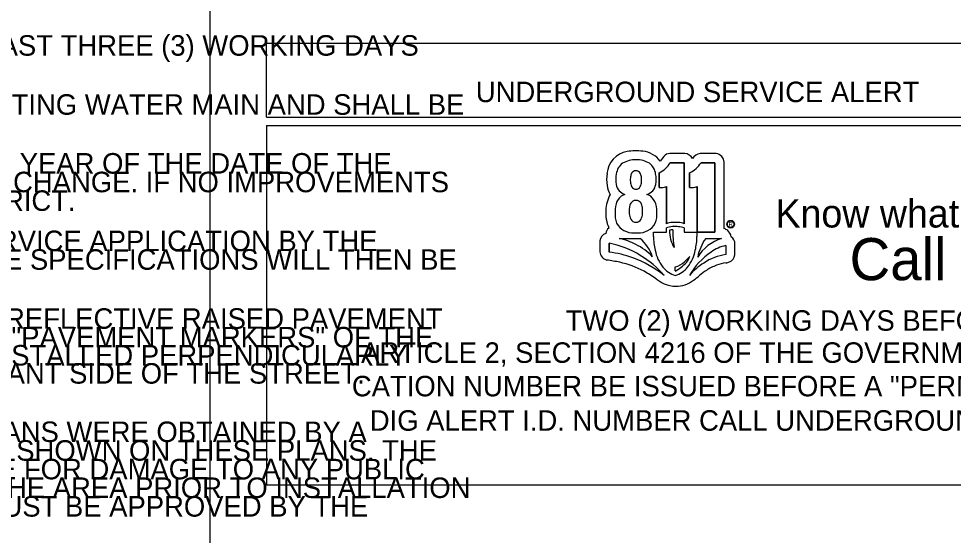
# Model space of a CAD drawing. Extents: x 837 to 1117, y 1316 to 1424.
# Drawn here: x 853.74 to 859.2, y 1404.15 to 1407.17 of the extents above; entities that cross this region are included whole.
import ezdxf

# ---------------------------------------------------------------- set-up
doc = ezdxf.new("R2010")
doc.units = 0
for name, color, linetype in [('BASEMAP', 7, 'Continuous'), ('Border', 7, 'Continuous'), ('Call811-black', 7, 'Continuous'), ('LLINES', 7, 'Continuous'), ('TEXT', 7, 'Continuous')]:
    doc.layers.add(name, color=color, linetype=linetype)

msp = doc.modelspace()

# ---------------------------------------------------------------- linework, layer by layer
msp.add_line((855.1874, 1406.5437), (855.1874, 1404.4416))
at = {"layer": 'BASEMAP'}
for p, q in [((854.8567, 1399.867), (854.8567, 1420.0652)), ((855.1874, 1406.5937), (855.1874, 1407.0257)), ((855.1874, 1407.0257), (862.4354, 1407.0257)), ((855.1874, 1406.5937), (862.4354, 1406.5937)), ((855.1874, 1406.5437), (862.4354, 1406.5437)), ((855.1855, 1404.4416), (862.4345, 1404.4416))]:
    msp.add_line(p, q, dxfattribs=at)
at = {"layer": 'Call811-black'}
for p, q in [((857.5107, 1406.3636), (857.49, 1406.3364)), ((857.6341, 1406.3807), (857.5472, 1406.3807)), ((857.6797, 1406.3505), (857.6781, 1406.3505)), ((857.8174, 1406.3802), (857.7235, 1406.3802)), ((857.549, 1406.3269), (857.6297, 1406.3269)), ((857.6297, 1406.3269), (857.6297, 1405.9699)), ((857.7289, 1406.3269), (857.8097, 1406.3269)), ((857.8097, 1406.3269), (857.8097, 1405.9204)), ((857.8636, 1405.9408), (857.8636, 1406.33)), ((857.4844, 1406.1821), (857.4844, 1406.2682)), ((857.6619, 1406.1821), (857.6619, 1406.2682)), ((857.5261, 1405.9699), (857.5261, 1406.1875)), ((857.706, 1405.9204), (857.706, 1406.1875)), ((857.451, 1405.8952), (857.451, 1405.9193)), ((857.451, 1405.9193), (857.5261, 1405.9193)), ((857.5261, 1405.9193), (857.5261, 1405.9453)), ((857.6297, 1405.9453), (857.6297, 1405.9193)), ((857.6297, 1405.9193), (857.7048, 1405.9193)), ((857.7048, 1405.9193), (857.7048, 1405.8952)), ((857.8097, 1405.9204), (857.706, 1405.9204)), ((857.1375, 1405.8693), (857.1375, 1405.8054)), ((857.1905, 1405.8025), (857.1905, 1405.8558)), ((857.2508, 1405.884), (857.3735, 1405.884)), ((857.7561, 1405.8831), (857.8492, 1405.8831)), ((857.9273, 1405.7867), (857.9273, 1405.8519)), ((857.8738, 1405.8415), (857.8738, 1405.7886))]:
    msp.add_line(p, q, dxfattribs=at)
for points in [[(857.5107, 1406.3636), (857.49, 1406.3364)], [(857.6341, 1406.3807), (857.5472, 1406.3807)], [(857.6797, 1406.3505), (857.6781, 1406.3505)], [(857.8174, 1406.3802), (857.7235, 1406.3802)], [(857.6297, 1405.9699), (857.6297, 1406.3269), (857.549, 1406.3269)], [(857.706, 1405.9204), (857.8097, 1405.9204), (857.8097, 1406.3269), (857.7289, 1406.3269)], [(857.8636, 1405.9408), (857.8636, 1406.33)], [(857.4844, 1406.2682), (857.4844, 1406.1821)], [(857.6619, 1406.2682), (857.6619, 1406.1821)], [(857.5261, 1406.1875), (857.5261, 1405.9699)], [(857.706, 1406.1875), (857.706, 1405.9204)], [(857.451, 1405.8952), (857.451, 1405.9193), (857.5261, 1405.9193), (857.5261, 1405.9453)], [(857.6297, 1405.9453), (857.6297, 1405.9193), (857.7048, 1405.9193), (857.7048, 1405.8952)], [(857.1375, 1405.8693), (857.1375, 1405.8054)], [(857.1905, 1405.8558), (857.1905, 1405.8025)], [(857.2508, 1405.884), (857.3735, 1405.884)], [(857.7561, 1405.8831), (857.8492, 1405.8831)], [(857.9273, 1405.7867), (857.9273, 1405.8519)], [(857.8738, 1405.8415), (857.8738, 1405.7886)], [(857.578, 1405.693), (857.5783, 1405.7168)]]:
    msp.add_lwpolyline(points, dxfattribs=at)
for radius in [0.0224, 0.0224, 0.0191, 0.0191]:
    msp.add_circle((857.9019, 1405.967), radius, dxfattribs=at)
for centre, radius, start, end in [((857.3207, 1406.2516), 0.1425, 99.999, 175.1926), ((857.3207, 1406.2516), 0.1425, 99.999, 175.1926), ((857.349, 1406.0779), 0.3185, 82.8327, 99.5813), ((857.349, 1406.0779), 0.3185, 82.8327, 99.5813), ((857.3717, 1406.246), 0.1489, 37.4108, 83.4439), ((857.3717, 1406.246), 0.1489, 37.4108, 83.4439), ((857.3437, 1406.2018), 0.1422, 87.8118, 121.4594), ((857.3437, 1406.2018), 0.1422, 87.8118, 121.4594), ((857.353, 1406.2026), 0.1414, 58.4897, 91.5654), ((857.353, 1406.2026), 0.1414, 58.4897, 91.5654), ((857.5475, 1406.3322), 0.0484, 90.4592, 139.5917), ((857.5475, 1406.3322), 0.0484, 90.4592, 139.5917), ((857.6301, 1406.3276), 0.0532, 25.4835, 85.607), ((857.6301, 1406.3276), 0.0532, 25.4835, 85.607), ((857.7279, 1406.3266), 0.0538, 94.7078, 153.6211), ((857.7279, 1406.3266), 0.0538, 94.7078, 153.6211), ((857.8103, 1406.3273), 0.0534, 2.8738, 82.3381), ((857.8103, 1406.3273), 0.0534, 2.8738, 82.3381), ((857.3231, 1406.2502), 0.0905, 126.3161, 173.2477), ((857.3231, 1406.2502), 0.0905, 126.3161, 173.2477), ((857.3733, 1406.2502), 0.0905, 6.7523, 53.6839), ((857.3733, 1406.2502), 0.0905, 6.7523, 53.6839), ((857.4264, 1406.3969), 0.1412, 294.2543, 330.2691), ((857.4264, 1406.3969), 0.1412, 294.2543, 330.2691), ((857.6032, 1406.4028), 0.1469, 293.5734, 328.8767), ((857.6032, 1406.4028), 0.1469, 293.5734, 328.8767), ((857.4313, 1406.229), 0.2549, 172.2103, 188.1816), ((857.4313, 1406.229), 0.2549, 172.2103, 188.1816), ((857.3928, 1406.229), 0.1627, 168.7247, 190.4792), ((857.3928, 1406.229), 0.1627, 168.7247, 190.4792), ((857.4461, 1406.2268), 0.131, 172.09, 185.2177), ((857.4461, 1406.2268), 0.131, 172.09, 185.2177), ((857.3776, 1406.2363), 0.0618, 152.1584, 172.0655), ((857.3776, 1406.2363), 0.0618, 152.1584, 172.0655), ((857.3468, 1406.2523), 0.0271, 87.8996, 151.6932), ((857.3468, 1406.2523), 0.0271, 87.8996, 151.6932), ((857.3494, 1406.2522), 0.0272, 28.3588, 93.3211), ((857.3494, 1406.2522), 0.0272, 28.3588, 93.3211), ((857.3187, 1406.2363), 0.0618, 7.9345, 27.8416), ((857.3187, 1406.2363), 0.0618, 7.9345, 27.8416), ((857.2502, 1406.2268), 0.131, 354.7823, 7.91), ((857.2502, 1406.2268), 0.131, 354.7823, 7.91), ((857.3035, 1406.229), 0.1627, 349.5208, 11.2753), ((857.3035, 1406.229), 0.1627, 349.5208, 11.2753), ((857.311, 1406.2117), 0.1334, 188.1816, 212.2335), ((857.311, 1406.2117), 0.1334, 188.1816, 212.2335), ((857.3021, 1406.2091), 0.07, 187.8977, 254.9735), ((857.3021, 1406.2091), 0.07, 187.8977, 254.9735), ((857.3835, 1406.2172), 0.0679, 181.9453, 206.7716), ((857.3835, 1406.2172), 0.0679, 181.9453, 206.7716), ((857.3484, 1406.2009), 0.0292, 209.2686, 270.3024), ((857.3484, 1406.2009), 0.0292, 209.2686, 270.3024), ((857.3478, 1406.2009), 0.0293, 271.4639, 330.7182), ((857.3478, 1406.2009), 0.0293, 271.4639, 330.7182), ((857.3128, 1406.2172), 0.0679, 333.2284, 358.0547), ((857.3128, 1406.2172), 0.0679, 333.2284, 358.0547), ((857.3942, 1406.2091), 0.07, 285.0265, 352.1023), ((857.3942, 1406.2091), 0.07, 285.0265, 352.1023), ((857.4943, 1406.2702), 0.0887, 263.562, 290.9659), ((857.4943, 1406.2702), 0.0887, 263.562, 290.9659), ((857.6725, 1406.2804), 0.0988, 263.8986, 289.847), ((857.6725, 1406.2804), 0.0988, 263.8986, 289.847), ((857.3502, 1406.048), 0.178, 148.69, 179.574), ((857.3502, 1406.048), 0.178, 148.69, 179.574), ((857.3087, 1406.0676), 0.0779, 108.4812, 145.0863), ((857.3087, 1406.0676), 0.0779, 108.4812, 145.0863), ((857.3877, 1406.0676), 0.0779, 34.9137, 71.5188), ((857.3877, 1406.0676), 0.0779, 34.9137, 71.5188), ((857.3302, 1406.0538), 0.1035, 145.6767, 179.0533), ((857.3302, 1406.0538), 0.1035, 145.6767, 179.0533), ((857.4646, 1406.0435), 0.1561, 172.09, 185.2177), ((857.4646, 1406.0435), 0.1561, 172.09, 185.2177), ((857.3829, 1406.0549), 0.0737, 152.1584, 172.0655), ((857.3829, 1406.0549), 0.0737, 152.1584, 172.0655), ((857.3462, 1406.0739), 0.0323, 87.8996, 151.6932), ((857.3462, 1406.0739), 0.0323, 87.8996, 151.6932), ((857.3493, 1406.0739), 0.0324, 28.3588, 93.3211), ((857.3493, 1406.0739), 0.0324, 28.3588, 93.3211), ((857.3127, 1406.0549), 0.0737, 7.9345, 27.8416), ((857.3127, 1406.0549), 0.0737, 7.9345, 27.8416), ((857.231, 1406.0435), 0.1561, 354.7823, 7.91), ((857.231, 1406.0435), 0.1561, 354.7823, 7.91), ((857.3661, 1406.0538), 0.1035, 0.9467, 34.3233), ((857.3661, 1406.0538), 0.1035, 0.9467, 34.3233), ((857.3974, 1406.0327), 0.2258, 175.7868, 203.0663), ((857.3974, 1406.0327), 0.2258, 175.7868, 203.0663), ((857.44, 1406.031), 0.2146, 173.4284, 191.4963), ((857.44, 1406.031), 0.2146, 173.4284, 191.4963), ((857.3899, 1406.0321), 0.0809, 181.9453, 206.7716), ((857.3899, 1406.0321), 0.0809, 181.9453, 206.7716), ((857.3056, 1406.0321), 0.0809, 333.2284, 358.0547), ((857.3056, 1406.0321), 0.0809, 333.2284, 358.0547), ((857.2564, 1406.031), 0.2146, 348.5037, 6.5716), ((857.2564, 1406.031), 0.2146, 348.5037, 6.5716), ((857.3225, 1406.0141), 0.0963, 195.5875, 233.3016), ((857.3225, 1406.0141), 0.0963, 195.5875, 233.3016), ((857.3481, 1406.0127), 0.0348, 209.2686, 270.3024), ((857.3481, 1406.0127), 0.0348, 209.2686, 270.3024), ((857.3474, 1406.0127), 0.0349, 271.4639, 330.7182), ((857.3474, 1406.0127), 0.0349, 271.4639, 330.7182), ((857.3739, 1406.0141), 0.0963, 306.6984, 344.4125), ((857.3739, 1406.0141), 0.0963, 306.6984, 344.4125), ((857.5498, 1405.9216), 0.0538, 98.3212, 116.1927), ((857.5498, 1405.9216), 0.0538, 98.3212, 116.1927), ((857.5749, 1405.7816), 0.1959, 88.3567, 99.6507), ((857.5749, 1405.7816), 0.1959, 88.3567, 99.6507), ((857.5823, 1405.792), 0.1855, 80.2121, 90.547), ((857.5823, 1405.792), 0.1855, 80.2121, 90.547), ((857.606, 1405.9216), 0.0538, 63.8073, 81.6788), ((857.606, 1405.9216), 0.0538, 63.8073, 81.6788), ((857.1909, 1405.8628), 0.0539, 110.5293, 173.0158), ((857.1909, 1405.8628), 0.0539, 110.5293, 173.0158), ((857.2106, 1405.9119), 0.0386, 122.909, 178.0418), ((857.2106, 1405.9119), 0.0386, 122.909, 178.0418), ((857.3316, 1406.0366), 0.12, 236.207, 265.1802), ((857.3316, 1406.0366), 0.12, 236.207, 265.1802), ((857.346, 1406.1017), 0.1863, 262.4451, 271.0167), ((857.346, 1406.1017), 0.1863, 262.4451, 271.0167), ((857.3509, 1406.0956), 0.1802, 269.5148, 277.6277), ((857.3509, 1406.0956), 0.1802, 269.5148, 277.6277), ((857.3647, 1406.0366), 0.12, 274.8198, 303.793), ((857.3647, 1406.0366), 0.12, 274.8198, 303.793), ((857.5498, 1405.8971), 0.0538, 98.3212, 116.1927), ((857.5498, 1405.8971), 0.0538, 98.3212, 116.1927), ((857.5749, 1405.7571), 0.1959, 88.3567, 99.6507), ((857.5749, 1405.7571), 0.1959, 88.3567, 99.6507), ((857.5585, 1405.8967), 0.0372, 82.0234, 112.2206), ((857.7391, 1405.9285), 0.1947, 179.2441, 210.2904), ((858.1519, 1405.9236), 0.5883, 179.0296, 189.1158), ((857.5823, 1405.7674), 0.1855, 80.2121, 90.547), ((857.5823, 1405.7674), 0.1855, 80.2121, 90.547), ((857.606, 1405.8971), 0.0538, 63.8073, 81.6788), ((857.606, 1405.8971), 0.0538, 63.8073, 81.6788), ((857.8475, 1405.8798), 0.0631, 53.7627, 75.1967), ((857.8475, 1405.8798), 0.0631, 53.7627, 75.1967), ((857.8456, 1405.886), 0.0594, 7.3834, 48.7359), ((857.8456, 1405.886), 0.0594, 7.3834, 48.7359), ((857.0949, 1405.3391), 0.5255, 57.9733, 79.5163), ((857.0949, 1405.3391), 0.5255, 57.9733, 79.5163), ((857.1558, 1405.4833), 0.4117, 62.33, 76.6551), ((857.1558, 1405.4833), 0.4117, 62.33, 76.6551), ((857.2052, 1405.5515), 0.3286, 43.0467, 64.4523), ((857.2052, 1405.5515), 0.3286, 43.0467, 64.4523), ((857.1972, 1405.6888), 0.263, 19.3184, 47.9077), ((857.1972, 1405.6888), 0.263, 19.3184, 47.9077), ((857.8149, 1405.8978), 0.364, 180.4178, 193.2572), ((857.8149, 1405.8978), 0.364, 180.4178, 193.2572), ((857.3409, 1405.8978), 0.364, 346.7428, 359.5822), ((857.3409, 1405.8978), 0.364, 346.7428, 359.5822), ((857.9212, 1405.6451), 0.2486, 106.8433, 148.53), ((857.9888, 1405.7179), 0.2854, 144.6348, 168.4777), ((857.9212, 1405.6451), 0.2486, 106.8433, 148.53), ((857.9888, 1405.7179), 0.2854, 144.6348, 168.4777), ((857.8775, 1405.8517), 0.0499, 0.2357, 57.1812), ((857.8775, 1405.8517), 0.0499, 0.2357, 57.1812), ((857.1902, 1405.8086), 0.0528, 183.4717, 256.8514), ((857.1902, 1405.8086), 0.0528, 183.4717, 256.8514), ((857.1395, 1405.2719), 0.533, 69.1311, 84.5007), ((857.1395, 1405.2719), 0.533, 69.1311, 84.5007), ((857.6791, 1405.8548), 0.2222, 190.4857, 218.6347), ((857.6791, 1405.8548), 0.2222, 190.4857, 218.6347), ((857.4767, 1405.8548), 0.2222, 321.3653, 349.5143), ((857.4767, 1405.8548), 0.2222, 321.3653, 349.5143), ((858.0263, 1405.4545), 0.4229, 124.3323, 149.8558), ((858.0263, 1405.4545), 0.4229, 124.3323, 149.8558), ((857.9146, 1405.6313), 0.2141, 100.9877, 126.326), ((857.9146, 1405.6313), 0.2141, 100.9877, 126.326), ((856.7577, 1403.118), 2.6725, 79.3174, 80.9479), ((856.7577, 1403.118), 2.6725, 79.3174, 80.9479), ((857.12, 1405.1586), 0.6005, 62.6567, 77.1974), ((857.12, 1405.1586), 0.6005, 62.6567, 77.1974), ((857.1188, 1405.1791), 0.6272, 50.9726, 70.3844), ((857.1188, 1405.1791), 0.6272, 50.9726, 70.3844), ((857.0631, 1405.2743), 0.5973, 41.0274, 58.6813), ((857.0631, 1405.2743), 0.5973, 41.0274, 58.6813), ((857.4927, 1405.8699), 0.1964, 295.7354, 319.9002), ((857.5482, 1405.8348), 0.1217, 284.3512, 313.9705), ((857.3851, 1406.015), 0.3647, 312.7475, 319.6368), ((857.5701, 1405.8082), 0.0975, 318.3348, 342.4149), ((857.9451, 1405.4217), 0.3756, 122.1554, 139.2439), ((857.9451, 1405.4217), 0.3756, 122.1554, 139.2439), ((857.9143, 1405.4889), 0.3025, 97.6832, 123.9821), ((857.9143, 1405.4889), 0.3025, 97.6832, 123.9821), ((857.9317, 1405.4068), 0.3389, 99.6589, 109.4788), ((857.9317, 1405.4068), 0.3389, 99.6589, 109.4788), ((857.8665, 1405.8102), 0.0698, 276.8288, 293.6655), ((857.8665, 1405.8102), 0.0698, 276.8288, 293.6655), ((857.8762, 1405.7947), 0.0518, 290.7825, 351.1469), ((857.8762, 1405.7947), 0.0518, 290.7825, 351.1469), ((856.4097, 1404.0731), 1.8956, 56.1356, 58.6515), ((856.4097, 1404.0731), 1.8956, 56.1356, 58.6515), ((857.6212, 1405.8064), 0.1467, 217.9711, 252.8236), ((857.6212, 1405.8064), 0.1467, 217.9711, 252.8236), ((857.5346, 1405.8064), 0.1467, 287.1764, 322.0289), ((857.5346, 1405.8064), 0.1467, 287.1764, 322.0289), ((857.9423, 1405.4156), 0.335, 122.9567, 131.4897), ((857.9423, 1405.4156), 0.335, 122.9567, 131.4897), ((857.9204, 1405.4519), 0.2927, 110.3424, 123.2327), ((857.9204, 1405.4519), 0.2927, 110.3424, 123.2327), ((857.6089, 1405.8329), 0.2344, 232.4217, 246.1444), ((857.6089, 1405.8329), 0.2344, 232.4217, 246.1444), ((857.5627, 1405.8092), 0.21, 290.4356, 305.7025), ((857.5627, 1405.8092), 0.21, 290.4356, 305.7025), ((857.4885, 1405.9218), 0.3448, 304.793, 312.2432), ((857.4885, 1405.9218), 0.3448, 304.793, 312.2432), ((857.5772, 1405.7508), 0.1466, 244.4852, 271.9359), ((857.5772, 1405.7508), 0.1466, 244.4852, 271.9359), ((857.5824, 1405.7867), 0.1824, 269.938, 287.1165), ((857.5824, 1405.7867), 0.1824, 269.938, 287.1165)]:
    msp.add_arc(centre, radius, start, end, dxfattribs=at)

# ---------------------------------------------------------------- texts
at = {"layer": 'Border'}
for s, height, p in [("Know what's", 0.164287, (858.1642, 1405.9475)), ('Call', 0.24643, (858.5975, 1405.6392))]:
    msp.add_text(s, height=height, dxfattribs=at).set_placement(p)
at = {"layer": 'Call811-black'}
msp.add_text('R', height=0.0236, dxfattribs=at).set_placement((857.8902, 1405.9552))
at = {"layer": 'LLINES'}
for s, p in [('THE CONTRACTOR IS TO NOTIFY THE AGENCY, TELEPHONE (661-940-9270, LANCASTER) / (310-317-1389, MALIBU), AT LEAST THREE (3) WORKING DAYS', (844.2181, 1406.953)), ('UNDERGROUND SERVICE ALERT', (856.4113, 1406.6811)), ('THE CONTRACTOR SHALL VERIFY THE SIZE, TYPE, CLASS, PROTECTIVE LINING AND COATING, AND DEPTH OF THE EXISTING WATER MAIN AND SHALL BE', (844.2181, 1406.6073)), ('THE DEVELOPER MUST PROCEED WITH, AND COMPLETE, THE REQUIRED WATER SYSTEM IMPROVEMENTS WITHIN ONE YEAR OF THE DATE OF THE', (844.2216, 1406.263)), ('DISTRICT APPROVAL OF THE PLANS.  AFTER THE 12 - MONTH PERIOD, THE DISTRICT REQUIREMENTS ARE SUBJECT TO CHANGE. IF NO IMPROVEMENTS', (844.2181, 1406.1539)), ('HAVE COMMENCED WITHIN A 24-MONTH PERIOD FROM APPROVAL DATE, THE PLANS MUST BE RE-ISSUED BY THE DISTRICT.', (844.2181, 1406.0448)), ('METERED WATER SERVICE CONNECTIONS MAY ONLY BE INSTALLED AFTER RECEIPT AND PROCESSING OF WATER SERVICE APPLICATION BY THE', (844.2181, 1405.8093)), ('AGENCY AND PAYMENT OF APPLICABLE CHARGES.  IF SERVICES ARE NOT TO BE INSTALLED PER THIS PLAN, SEPARATE SPECIFICATIONS WILL THEN BE', (844.2174, 1405.7002)), ('WHERE PUBLIC FIRE HYDRANTS ARE INSTALLED OR UPGRADED, THE CONTRACTOR SHALL INSTALL A TWO-WAY BLUE REFLECTIVE RAISED PAVEMENT', (844.2331, 1405.3548)), ('MARKER ALSO COMMONLY CALLED "BLUE DOTS".  REFLECTORS SHALL COMPLY AND BE INSTALLED PER SECTION 214- "PAVEMENT MARKERS" OF THE', (844.2181, 1405.2457)), ('LATEST EDITION OF THE STANDARD SPECIFICATIONS FOR PUBLIC WORKS CONSTRUCTION.  ONE MARKER SHALL BE INSTALLED PERPENDICULARLY', (844.2247, 1405.1398)), ('OPPOSITE EACH HYDRANT, APPROXIMATELY 6 INCHES OFFSET FROM THE CENTERLINE OF THE STREET ON THE HYDRANT SIDE OF THE STREET.', (844.2247, 1405.0338)), ('THE EXISTENCE AND LOCATION OF ANY UNDERGROUND UTILITIES, PIPES AND/OR STRUCTURES SHOWN ON THESE PLANS WERE OBTAINED BY A', (844.2181, 1404.692)), ('SEARCH OF AVAILABLE RECORDS.  TO THE BEST OF OUR KNOWLEDGE, THERE ARE NO EXISTING UTILITIES EXCEPT AS SHOWN ON THESE PLANS. THE', (844.2181, 1404.5829)), ('CONTRACTOR SHALL ASCERTAIN THE TRUE LOCATION OF ANY UNDERGROUND UTILITIES AND SHALL BE RESPONSIBLE FOR DAMAGE TO ANY PUBLIC', (844.2275, 1404.4738)), ('OR PRIVATE UTILITIES, SHOWN OR NOT SHOWN HEREON. IT IS ALSO SUGGESTED THAT THE CONTRACTOR POTHOLE THE AREA PRIOR TO INSTALLATION', (844.2275, 1404.3647)), ('TO MAKE SURE CONNECTIONS AND CROSSINGS CAN BE MADE ACCORDING TO PLAN.  ANY CHANGES TO THE PLANS MUST BE APPROVED BY THE', (844.2181, 1404.2556))]:
    msp.add_text(s, height=0.12, dxfattribs=at).set_placement(p)
at = {"layer": 'TEXT'}
for s, p in [('TWO (2) WORKING DAYS BEFORE YOU DIG', (856.9364, 1405.3434)), ('ARTICLE 2, SECTION 4216 OF THE GOVERNMENT CODE REQUIRES A DIG ALERT IDENTIFI-', (855.7404, 1405.1555)), ('CATION NUMBER BE ISSUED BEFORE A "PERMIT TO EXCAVATE" WILL BE VALID.  FOR YOUR', (855.6864, 1404.9594)), ('DIG ALERT I.D. NUMBER CALL UNDERGROUND SERVICE ALERT AT THE NUMBER ABOVE.', (855.7913, 1404.7582))]:
    msp.add_text(s, height=0.12, dxfattribs=at).set_placement(p)

doc.saveas('drawing.dxf')
